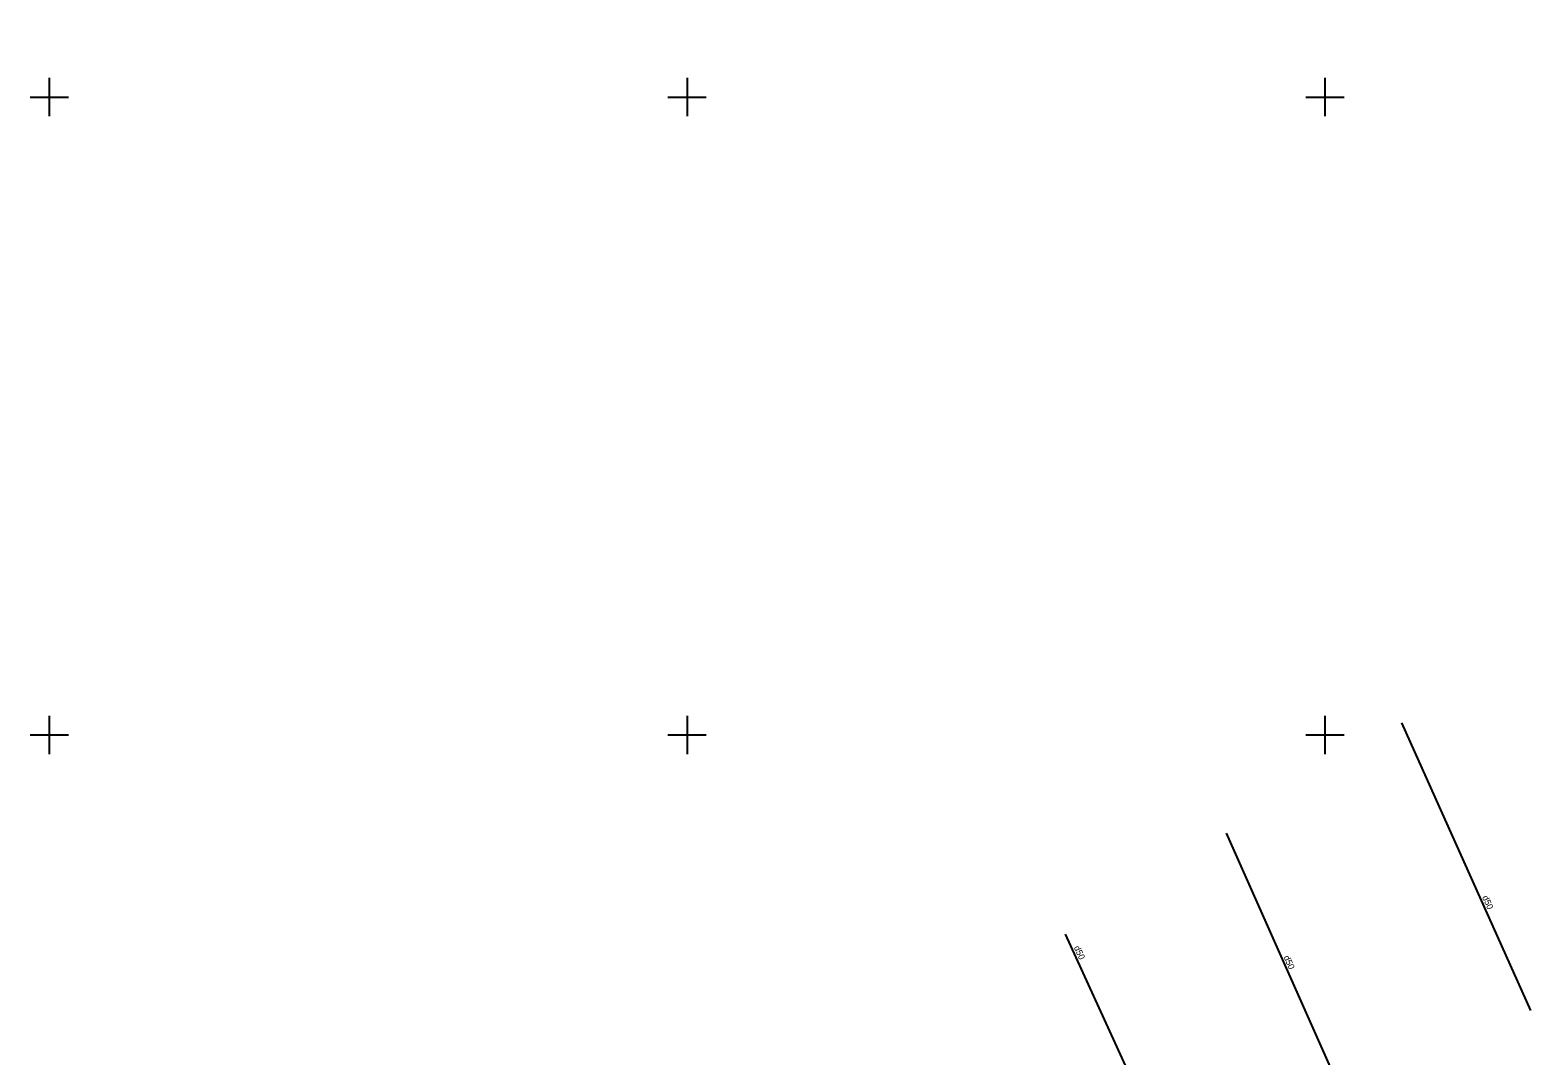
# Model space of a CAD drawing. Extents: x 469981 to 472086, y 246785 to 247785.
# Drawn here: x 471248.5 to 471366.7, y 247374.8 to 247455.3 of the extents above; entities that cross this region are included whole.
import ezdxf

# ---------------------------------------------------------------- set-up
doc = ezdxf.new("R2010")
doc.units = 0
for name, color, linetype in [('DREN_VADP_####_####_#', 7, 'Continuous'), ('DREN_VADP_####_TKST_#', 7, 'Continuous'), ('GEOD_ELEM_####_####_#', 7, 'Continuous'), ('RELJ_NOGA_####_####_#', 7, 'Continuous'), ('RELJ_NOGL_####_####_#', 7, 'Continuous')]:
    doc.layers.add(name, color=color, linetype=linetype)

msp = doc.modelspace()

# ---------------------------------------------------------------- linework, layer by layer
at = {"layer": 'DREN_VADP_####_####_#'}
for points in [[(471366.13, 247378.39), (471356.02, 247400.94)], [(471342.26, 247392.29), (471351.97, 247370.43)], [(471339.79, 247362.2), (471329.67, 247384.37)]]:
    msp.add_lwpolyline(points, dxfattribs=at)
at = {"layer": 'GEOD_ELEM_####_####_#'}
for p, q in [((471250, 247451.5), (471250, 247450)), ((471300, 247451.5), (471300, 247450)), ((471350, 247451.5), (471350, 247450)), ((471248.5, 247450), (471250, 247450)), ((471250, 247450), (471250, 247448.5)), ((471250, 247450), (471251.5, 247450)), ((471298.5, 247450), (471300, 247450)), ((471300, 247450), (471300, 247448.5)), ((471300, 247450), (471301.5, 247450)), ((471348.5, 247450), (471350, 247450)), ((471350, 247450), (471350, 247448.5)), ((471350, 247450), (471351.5, 247450)), ((471250, 247401.5), (471250, 247400)), ((471300, 247401.5), (471300, 247400)), ((471350, 247401.5), (471350, 247400)), ((471248.5, 247400), (471250, 247400)), ((471250, 247400), (471250, 247398.5)), ((471250, 247400), (471251.5, 247400)), ((471298.5, 247400), (471300, 247400)), ((471300, 247400), (471300, 247398.5)), ((471300, 247400), (471301.5, 247400)), ((471348.5, 247400), (471350, 247400)), ((471350, 247400), (471350, 247398.5)), ((471350, 247400), (471351.5, 247400))]:
    msp.add_line(p, q, dxfattribs=at)
at = {"layer": 'RELJ_NOGA_####_####_#'}
msp.add_spline([(471341.93, 247360.74), (471344.51, 247356.26), (471349.95, 247353.75), (471355.9, 247354.99), (471376.69, 247368.01), (471396.06, 247380.32), (471444.05, 247411.05), (471471.48, 247428.43), (471497.59, 247445.1), (471529.06, 247465.66), (471552.02, 247480.39), (471579.85, 247498.34), (471608.29, 247516.96), (471640.01, 247537.43), (471663.53, 247552.84), (471700.31, 247577.15), (471731.58, 247597), (471755.89, 247610.64), (471758.96, 247612.21)], degree=3, dxfattribs=at)
at = {"layer": 'RELJ_NOGL_####_####_#'}
msp.add_spline([(471342.51, 247361.02), (471345.4, 247356.89), (471350.22, 247354.86), (471355.25, 247356.42), (471376.01, 247368.36), (471395.6, 247380.99), (471443.66, 247411.57), (471471.28, 247429.25), (471497.37, 247445.87), (471528.27, 247466.83), (471551.61, 247481.24), (471579.42, 247499.1), (471607.69, 247517.41), (471639.59, 247538.32), (471662.84, 247553.56), (471699.58, 247577.98), (471731.35, 247598.06), (471755.71, 247611.43), (471758.27, 247612.73)], degree=3, dxfattribs=at)

# ---------------------------------------------------------------- texts
at = {"layer": 'DREN_VADP_####_TKST_#'}
for rotation, p in [(294.1616, (471362.31, 247387.28)), (294.5438, (471330.3, 247383.34)), (293.9628, (471346.74, 247382.58))]:
    msp.add_text('d50', height=0.5, rotation=rotation, dxfattribs=at).set_placement(p)

doc.saveas('drawing.dxf')
